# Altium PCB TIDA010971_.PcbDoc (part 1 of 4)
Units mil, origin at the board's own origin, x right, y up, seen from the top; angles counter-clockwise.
Board outline 4500 x 6000 mil, 2 copper layers (F.CU, B.CU), stack 60.617 mil thick; 280 components, 124 nets, 681 pads, 871 vias.
Unrouted connection lines stored in the file: 1.
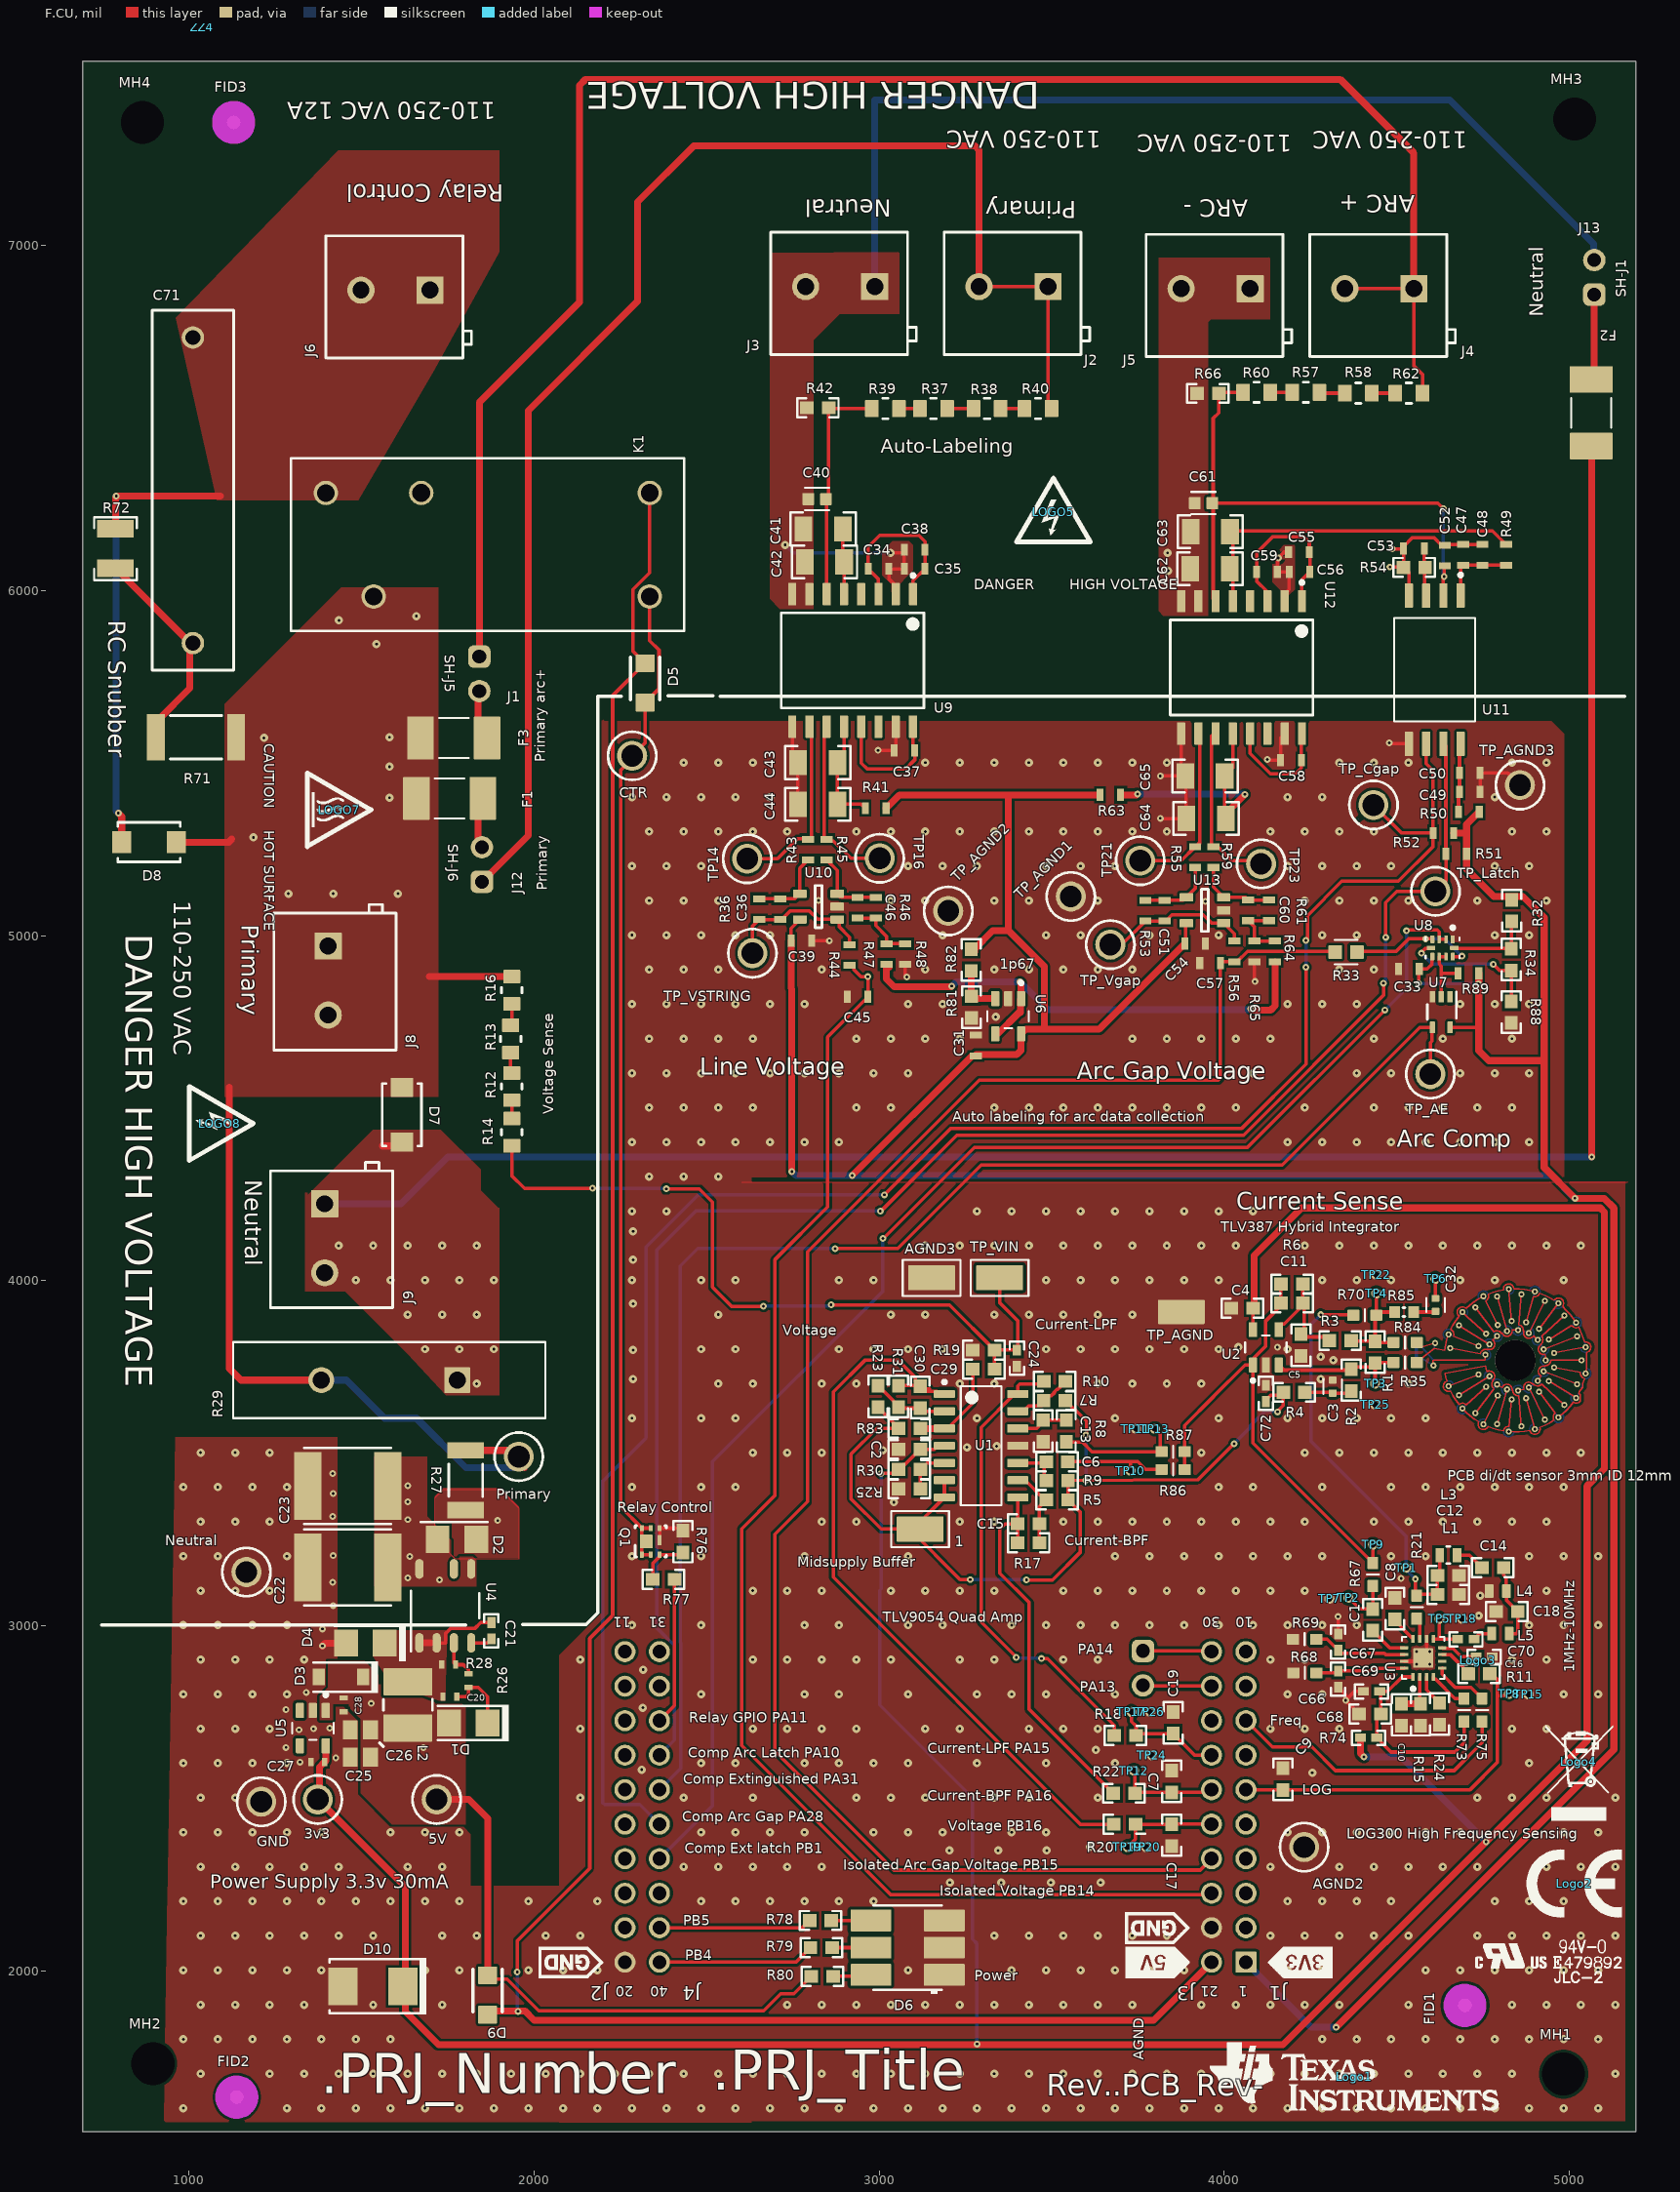
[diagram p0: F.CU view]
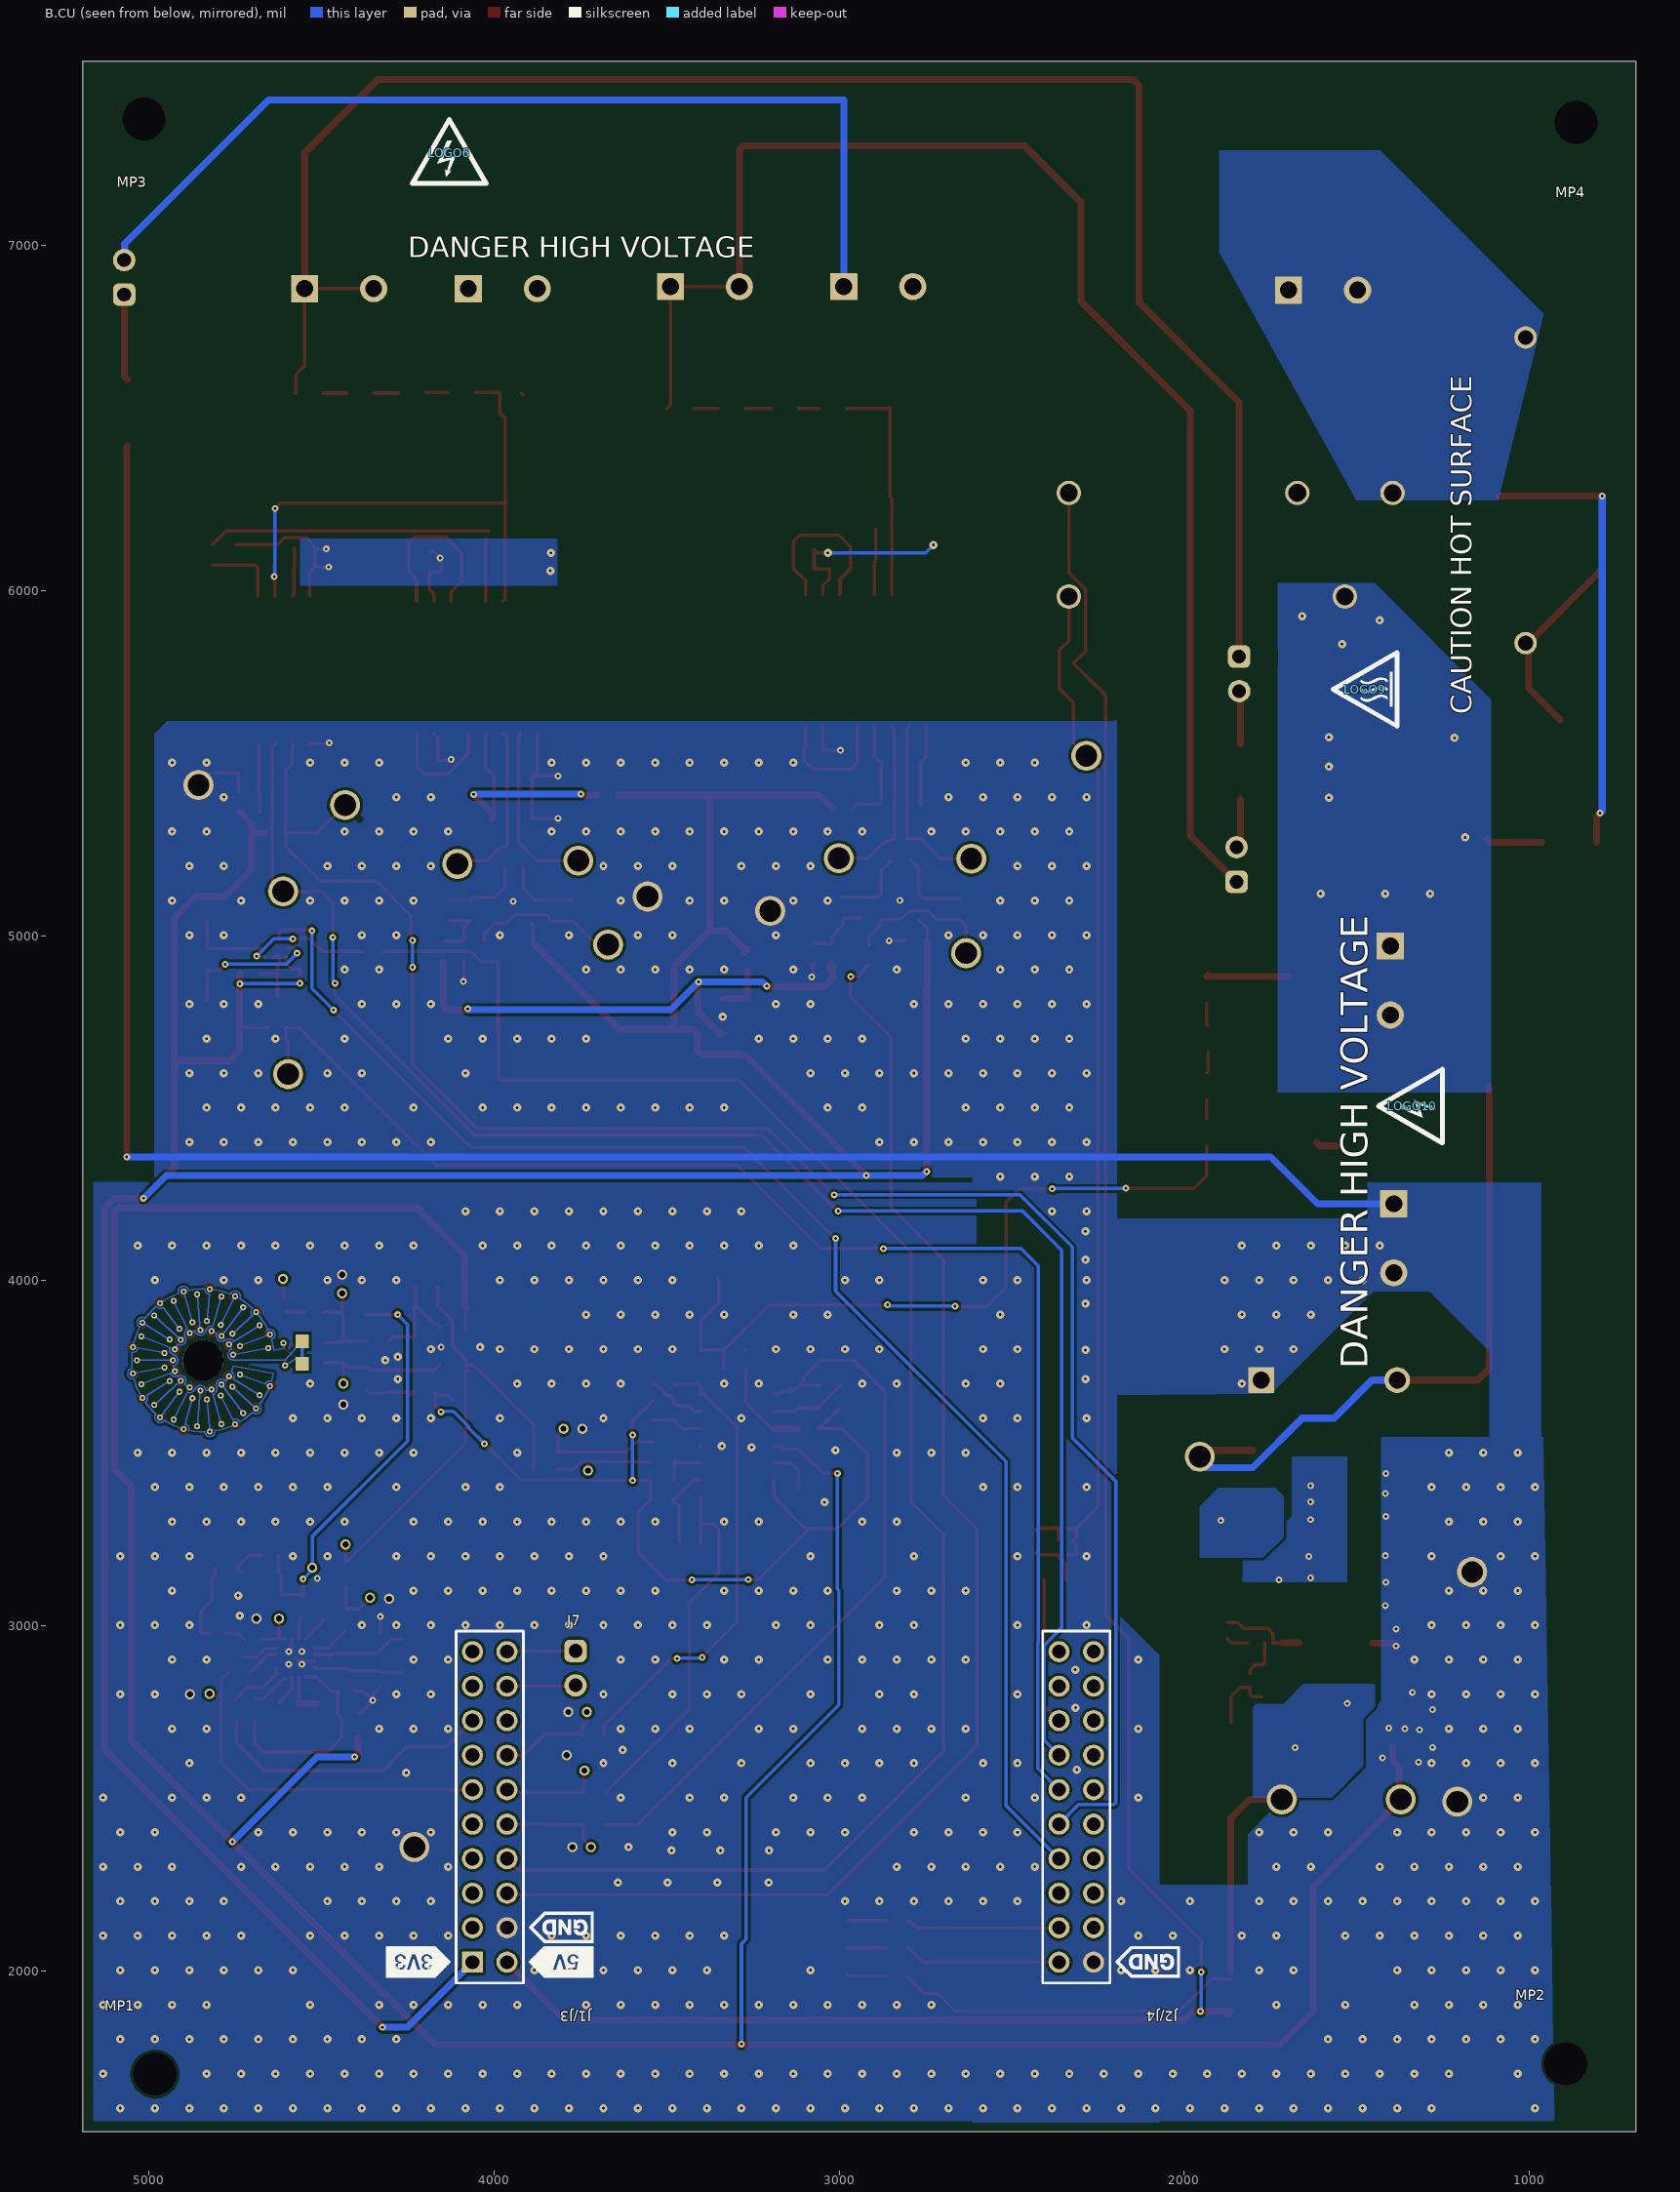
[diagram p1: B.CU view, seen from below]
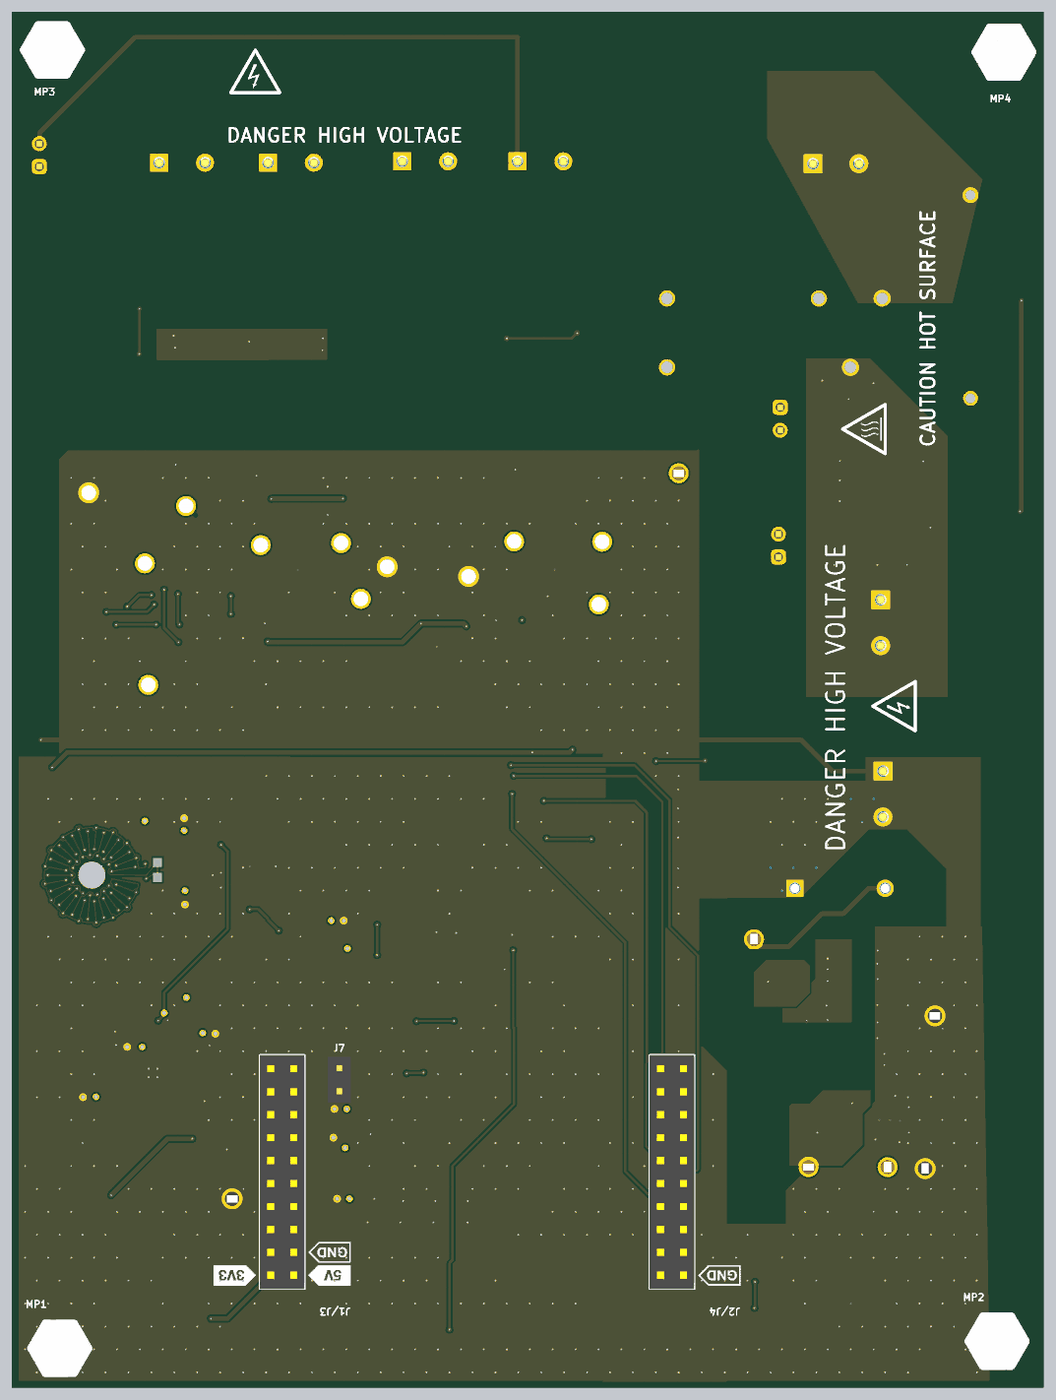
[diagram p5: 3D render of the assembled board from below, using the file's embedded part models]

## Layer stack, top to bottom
Top Solder: solder mask 0.4, Solder Resist, Dk 3.5
F.CU: signal copper 0.7087
Dielectric1: core 59.2, FR-4 High Tg, Dk 4.8
B.CU: signal copper 0.7087
Bottom Solder: solder mask 0.4, Solder Resist, Dk 3.5

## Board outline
692,1534 5192,1534 5192,7534 692,7534

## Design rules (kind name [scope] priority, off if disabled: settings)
AcuteAngle [All] p1: minimum=4.50000000000000E+0001 checktracksonly=FALSE
AssemblyTestPointUsage [All] p1: valid=2
BoardOutlineClearance BoardOutlineClearance_MountingHoles [OnCopper and InComponentClass('Mounting Holes')] p1: gap=39.37 ignorepadtopadclearanceinfootprint=FALSE
BoardOutlineClearance BoardOutlineClearance_Poly [OnCopper and IsPoly] p2: gap=25 ignorepadtopadclearanceinfootprint=FALSE
BoardOutlineClearance [OnCopper and Not InComponentClass('Logo') and not InComponentClass('FiducialMark') and not InRegion(1000,500,4000,800) and not InPoly] p3: gap=40 ignorepadtopadclearanceinfootprint=FALSE
Clearance Clearance_1 [InNetClass('low voltage') And OnMid vs InNetClass('high voltage') And OnMid] p1: gap=80 ignorepadtopadclearanceinfootprint=FALSE
Clearance Clearance_2 [InNetClass('low voltage') And (ExistsOnLayer('F.CU') Or ExistsOnLayer('B.CU')) vs InNetClass('high voltage') And (ExistsOnLayer('F.CU') Or ExistsOnLayer('B.CU'))] p2: gap=80 ignorepadtopadclearanceinfootprint=FALSE
Clearance Clearance_3 [InNetClass('low voltage') vs InNetClass('high voltage')] p3: gap=10 ignorepadtopadclearanceinfootprint=FALSE except(0: Arc-Hole Track-Hole SMDPad-Hole THPad-Hole Via-Hole Fill-Hole Poly-Hole Region-Hole Text-Hole)
Clearance Clearance_4 [OnMid vs OnMid] p4: gap=7.87 ignorepadtopadclearanceinfootprint=FALSE
Clearance Clearance_5 [(ExistsOnLayer('F.CU') Or ExistsOnLayer('B.CU')) vs (ExistsOnLayer('F.CU') Or ExistsOnLayer('B.CU'))] p5: gap=7.87 ignorepadtopadclearanceinfootprint=FALSE
Clearance [All] p6: gap=10 ignorepadtopadclearanceinfootprint=FALSE except(0: Arc-Hole Track-Hole SMDPad-Hole THPad-Hole Via-Hole Fill-Hole Poly-Hole Region-Hole Text-Hole)
ComponentClearance ComponentClearance_MountingHoles_FiducialMarks [InComponentClass('Mounting Holes') vs InComponentClass('FiducialMark')] p1: gap=50 collisioncheckmode=3 verticalgap=10 showdistances=FALSE
ComponentClearance ComponentClearance_Shunt [InComponentClass('Header') vs InComponentClass('Shunt')] p2: gap=0 collisioncheckmode=3 verticalgap=0 showdistances=FALSE
ComponentClearance ComponentClearance_Logo [InComponentClass('Logo')] p3: gap=30 collisioncheckmode=3 verticalgap=10 showdistances=FALSE
ComponentClearance ComponentClearance_ScrewToNut [(HasFootprint('NY PMS 440 0025 PH')) vs (HasFootprint('Keystone_1902C'))] p4: gap=5 collisioncheckmode=3 verticalgap=10 showdistances=FALSE
ComponentClearance ComponentClearance_MountingHoles [InComponentClass('Mounting Holes')] p5: gap=100 collisioncheckmode=3 verticalgap=100000 showdistances=FALSE
ComponentClearance ComponentClearance_SmallPassives [HasFootprint('0201*') or HasFootprint('0402*') or HasFootprint('0508') or HasFootprint('0603*') or HasFootprint('0612') or HasFootprint('0805*') or HasFootprint('0815*') or HasFootprint('0830*') or HasFootprint('1206*') or HasFootprint('1210*') or HasFootprint('1808*') or HasFootprint('1812*') or HasFootprint('1825*') or HasFootprint('2010*') or HasFootprint('2220*') or HasFootprint('2225*') or HasFootprint('2512*') or HasFootprint('2728*') or HasFootprint('3518*') vs HasFootprint('0201*') or HasFootprint('0402*') or HasFootprint('0508') or HasFootprint('0603*') or HasFootprint('0612') or HasFootprint('0805*') or HasFootprint('0815*') or HasFootprint('0830*') or HasFootprint('1206*') or HasFootprint('1210*') or HasFootprint('1808*') or HasFootprint('1812*') or HasFootprint('1825*') or HasFootprint('2010*') or HasFootprint('2220*') or HasFootprint('2225*') or HasFootprint('2512*') or HasFootprint('2728*') or HasFootprint('3518*')] p6: gap=14.96 collisioncheckmode=3 verticalgap=10 showdistances=FALSE
ComponentClearance ComponentClearance_THtoSMT [IsThruComponent vs IsSMTComponent] p7: gap=30 collisioncheckmode=3 verticalgap=30 showdistances=FALSE
ComponentClearance ComponentClearance_THtoTH [IsThruComponent vs IsThruComponent] p8: gap=20 collisioncheckmode=3 verticalgap=30 showdistances=FALSE
ComponentClearance [All] p9: gap=20 collisioncheckmode=3 verticalgap=10 showdistances=FALSE
FabricationTestPointUsage TestPointUsage [All] p1: valid=2 allowmultiple=FALSE
FabricationTestpoint Testpoint [All] p1: side=3 testpointundercomponent=TRUE minsize=40 maxsize=100 preferedsize=60 minholesize=0 maxholesize=40 preferedholesize=32 testpointgrid=1 allowsidetop=TRUE allowsidebottom=TRUE usegrid=TRUE gridtolerance=0.01
FanoutControl Fanout_LCC [IsLCC] p1: bgadir=Out bgaviamode=Centered fanoutstyle=Auto fanoutdirection=Alternating viagrid=1 // Fanout_LCC (Default Rule)
FanoutControl Fanout_BGA [IsBGA] p2: bgadir=Out bgaviamode=Centered fanoutstyle=Auto fanoutdirection=Alternating viagrid=1 // Fanout_BGA (Default Rule)
FanoutControl Fanout_Default [All] p4: bgadir=Out bgaviamode=Centered fanoutstyle=Auto fanoutdirection=Alternating viagrid=1 // Fanout_Default (Default Rule)
FanoutControl Fanout_Small [(CompPinCount < 5)] p5: bgadir=Out bgaviamode=Centered fanoutstyle=Auto fanoutdirection=OutThenIn viagrid=1 // Fanout_Small (Default Rule)
HoleSize [All] p1: absolutevalues=TRUE maxlimit=251 minlimit=7.87 maxpercent=80.000 minpercent=20.000
MinimumAnnularRing MinimumAnnularRing_ThermalPadVias [IsVia and InAnyComponent] p1: minimumring=5.91
MinimumAnnularRing [All] p2: minimumring=4.92
MinimumSolderMaskSliver MinimumSolderMaskSliver_Logo [InComponentClass('Logo') vs InComponentClass('Logo')] p1: minsoldermaskwidth=0.7
MinimumSolderMaskSliver [All] p2: minsoldermaskwidth=3.94
PlaneConnect [All] p1: planeconnectstyle=Direct reliefexpansion=10 reliefentries=4 reliefconductorwidth=10 reliefairgap=10
PolygonConnect PolygonConnect_1 [All vs IsNamedPolygon('F.CU_GND_ISO_AMC23C12_P064')] p1: thpad.connectstyle=Direct thpad.reliefconductorwidth=10 thpad.reliefentries=4 thpad.polygonreliefangle="90 Angle" thpad.airgapwidth=5 smdpad.connectstyle=Direct smdpad.reliefconductorwidth=10 smdpad.reliefentries=4 smdpad.polygonreliefangle="90 Angle" smdpad.airgapwidth=10 via.connectstyle=Relief via.reliefconductorwidth=10 via.reliefentries=4 via.polygonreliefangle="90 Angle" via.airgapwidth=10
PolygonConnect [All] p2: connectstyle=Direct reliefconductorwidth=10 reliefentries=4 polygonreliefangle="90 Angle" airgapwidth=10
RoutingVias [All] p1: holewidth=28 width=50 viastyle="Through Hole" minholewidth=28 minwidth=50 maxholewidth=28 maxwidth=50 useviatemplates=TRUE viatemplateguid#1={BF80594A-C1D7-457B-8FD0-876E30155DD2} viatemplatename#1=v50h20
SilkToBoardRegionClearance [Not ((IsComment or IsDesignator) And (Hide <> 'False')) and not InRegion(1000,500,4000,800)] p1:
SilkToSilkClearance SilkToSilkClearance_Pb-FreeLogo [(HasFootprint('Pb-Free_Overlay_Medium') OR HasFootprint('Pb-Free_Overlay_Small')) vs (HasFootprint('Pb-Free_Overlay_Medium') OR HasFootprint('Pb-Free_Overlay_Small'))] p1: silktosilkclearance=0
SilkToSilkClearance [All] p2: silktosilkclearance=3.94
SilkToSolderMaskClearance SilkToComponentPadClearance [(IsPad or IsFill or IsRegion) and InAnycomponent] p1: minsilkscreentomaskgap=5 clearancetoexposedcopper=TRUE
SilkToSolderMaskClearance "Silk to Solder Mask Opening" [All] p2: minsilkscreentomaskgap=3.94 clearancetoexposedcopper=FALSE
SolderMaskExpansion SolderMask_tentVias [IsVia] p1: expansion=4 istentingtop=TRUE
SolderMaskExpansion [All] p2: expansion=1.97 istentingtop=FALSE
UnRoutedNet [All] p1: checkbadconnections=TRUE
Width MaxMinWidth_1 [All] p1: maxlimit=20 minlimit=3.94 preferedwidth=10 minimp=50.000000 maximp=50.000000 favimp=50.000000
Width [All] p2: maxlimit=20 minlimit=5 preferedwidth=10 minimp=50.000000 maximp=50.000000 favimp=50.000000
15 further rules are at their usual default settings.

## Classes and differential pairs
net class "low voltage": 3v3 3v3USB 5v_led 5vUSB ADC_Log "ADC_Voltage sense" AFEen BP_in COMP_VGap COMP_VGap_LATCH COMP_VGap_VString Current_BP Current_LP FreqDetect GND_iso_AMC23C12 LNA_en LNA_O Log+ Log- midSupply NetC1_1 NetC1_2 NetC3_2 NetC5_2 NetC6_1 NetC8_2 NetC10_2 NetC13_2 NetC14_1 NetC14_2 NetC15_1 NetC15_2 NetC20_1 NetC20_2 NetC21_1 NetC24_1 NetC29_1 NetC30_1 NetC30_2 NetC34_1 NetC34_2 NetC36_1 NetC36_2 NetC37_1 NetC40_2 NetC41_1 NetC43_1 NetC46_1 NetC46_2 NetC47_1 NetC49_1 NetC51_1 NetC51_2 NetC52_1 NetC53_1 NetC55_1 NetC58_1 NetC60_1 NetC60_2 NetC64_1 NetC68_2 NetC70_2 NetC71_1 NetCTR_1 NetD6_4 NetD6_5 NetD6_6 NetF1_1 NetF2_1 NetF3_1 NetJ1_1 NetJ2_1 NetQ1_3 NetR7_2 NetR10_2 NetR11_1 NetR12_1 NetR12_2 NetR13_1 NetR24_1 NetR25_2 NetR26_1 NetR32_1 NetR33_1 NetR37_1 NetR37_2 NetR38_1 NetR57_1 NetR57_2 NetR58_1 NetR73_1 NetR75_2 PA13_UART0-TX_XDS PA14_UART0-RX_XDS relayGPIO Rogo+ Rogo- V_Gap V_String VCC_iso_AMC23C12 VGap_Diff_N VGap_Diff_P VString_Diff_N VString_Diff_P
net class "high voltage": hv2 HVIN NetD2_2 Primary RelayControl
component class Shunt: SH-J1 SH-J5 SH-J6
component class Header: J1 J7 J12 J13
component class FiducialMark: FID1 FID2 FID3
polygon class HighVoltage: F.CU_5V_P059
component class TIDA010971_Power: 3v3 5V C20 C21 C22 C23 C25 C26 C27 C28 D1 D2 D3 D4 D7 D10 GND J8 J9 L2 Neutral Primary R26 R27 R28 R29 U4 U5
component class TIDA010971_Connectors_MCU_Labeling: C71 CTR D5 D6 D8 D9 J1/J3 J2/J4 J6 J7 K1 Q1 R71 R72 R76 R77 R78 R79 R80
component class TIDA010971_AutoLabeling: C31 C33 C34 C35 C36 C37 C38 C39 C40 C41 C42 C43 C44 C45 C46 C47 C48 C49 C50 C51 C52 C53 C54 C55 C56 C57 C58 C59 C60 C61 C62 C63 C64 C65 F1 F2 F3 J1 J2 J3 J4 J5 J12 J13 R32 R33 R34 R36 R37 R38 R39 R40 R41 R42 R43 R44 R45 R46 R47 R48 R49 R50 R51 R52 R53 R54 R55 R56 R57 R58 R59 R60 R61 R62 R63 R64 R65 R66 R81 R82 R88 R89 SH-J1 SH-J5 SH-J6 TP14 TP16 TP21 TP23 TP_AE TP_AGND1 TP_AGND2 TP_AGND3 TP_Cgap TP_Latch TP_Vgap TP_VSTRING U6 U7 U8 U9 U10 U11 U12 U13
component class TIDA010971_AFE: 1 AGND2 AGND3 C1 C2 C3 C4 C5 C6 C7 C8 C9 C10 C11 C12 C13 C14 C15 C16 C17 C18 C19 C24 C29 C30 C32 C66 C67 C68 C69 C70 C72 L1 L3 L4 L5 R1 R2 R3 R4 R5 R6 R7 R8 R9 R10 R11 R12 R13 R14 R15 R16 R17 R18 R19 R20 R21 R22 R23 R24 R25 R30 R31 R35 R67 R68 R69 R70 R73 R74 R75 R83 R84 R85 R86 R87 TP1 TP2 TP3 TP4 TP5 TP6 TP7 TP8 TP9 TP10 TP11 TP12 TP13 TP15 TP17 TP18 TP19 TP20 TP22 TP24 TP25 TP26 TP_AGND TP_VIN U1 U2 U3
component class Logo: Logo1
component class TIDA010971_Hardware: FID1 FID2 FID3 Logo1 Logo2 Logo3 Logo4 LOGO5 LOGO6 LOGO7 LOGO8 LOGO9 LOGO10 MH1 MH2 MH3 MH4 MP1 MP2 MP3 MP4 ZZ1 ZZ2 ZZ3 ZZ4
component class AssemblyNote: ZZ1 ZZ2 ZZ3 ZZ4

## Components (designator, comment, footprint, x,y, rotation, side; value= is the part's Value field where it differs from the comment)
1 "S1751-46R" FP-S1751-46R_SMT_TEST_POINT_3MM25_1MM65-MFG 3118.56,3279.95 r180 top
3v3 "5010" Keystone5010 1372.77,2496.66 r180 top
5V "5010" Keystone5010 1717.36,2496.66 r90 top
AGND2 "HS1_GND" Keystone5006 4231.31,2358.55 r0 top
AGND3 "S1751-46R" FP-S1751-46R_SMT_TEST_POINT_3MM25_1MM65-MFG 3151.52,4008.52 r180 top
C1 "GRM1885C1E102JA01D" 0603 4430.17,3017.24 r90 top value=1000pF
C2 "0603ZC104KAT2A" 0603 3087.47,3511.35 r0 top value=0.1uF
C3 "GMC04X7R105K10NT" FP-GMC04X7R105K10NT_0402-MFG 4314,3693 r270 top value=1µF
C4 "0603ZC104KAT2A" 0603 4052,3920.28 r0 top value=0.1uF
C5 "C0603C271J5GACTU" 0603 4222,3813.5 r90 top value=270pF
C6 "06035A101JAT2A" 0603 3515.33,3475.54 r0 top value=100pF
C7 "06035A101JAT2A" 0603 3847.78,2548.81 r90 top value=100pF
C8 "06035C104JAT2A" 0603 4493.95,3049.8 r270 top value=0.1uF
C9 "GRM1885C1H470JA01D" 0603 4169.78,2555.46 r90 top value=47pF
C10 "GRM1885C1E102JA01D" 0603 4513.58,2742.1 r90 top value=1000pF
C11 "C0603C271J5GACTU" 0603 4196.22,3935.08 r0 top value=270pF
C12 "GRM1885C1H131JA01D" 0603 4649.04,3145.8 r0 top value=130pF
C13 "0603ZC104KAT2A" 0603 3475.33,3564.54 r90 top value=0.1uF
C14 "GRM1885C1H152JA01D" 0603 4778,3168.28 r180 top value=1500pF
C15 "06035A470JAT2A" 0603 3432.7,3295.43 r0 top value=47pF
C16 "CL05B392KB5NNNC" 0402 4753,2910 r0 top value=3900pF
C17 "GRM1885C1H470JA01D" 0603 3847.28,2393 r270 top value=47pF
C18 "GRM1885C1H331JA01D" 0603 4818.95,3041 r180 top value=330pF
C19 "06035A101JAT2A" 0603 3851.56,2718.73 r90 top value=100pF
C20 "GRM155R71H153KA12D" 0402S 1755.43,2795.15 r180 top value=0.015uF
C21 "GRM155R61C105MA12D" 0402 1875.74,2985.95 r90 top value=1uF
C22 "CKG57NX7T2W225M500JH" CKG57N 1459.61,3168.87 r180 top value=2.2uF
C23 "CKG57NX7T2W225M500JH" CKG57N 1459.61,3405.37 r180 top value=2.2uF
C24 "GRM1555C1H2R4CA01D" 0402 3398.7,3775.36 r270 top value=2.4pF
C25 "GRM21BR61A476ME15L" 0805L 1496.3,2618.71 r180 top value=47uF
C26 "GRM21BR61A476ME15L" 0805L 1496.3,2698.37 r180 top value=47uF
C27 "GRM155R61A105ME15D" 0402S 1372.77,2604.93 r180 top value=1uF
C28 "GRM155R61A104KA01D" 0402S 1447.99,2771.12 r270 top value=0.1uF
C29 "CL10B103KB8NCNC" 0603 3302.8,3743.93 r0 top value=0.01uF
C30 "GRM1885C1H470JA01D" 0603 3118.56,3662.23 r270 top value=47pF
C31 "C0603C104K5RACAUTO" 0603S 3280.22,4681.56 r90 top value=0.1uF
C32 "GMC04X7R105K10NT" FP-GMC04X7R105K10NT_0402-MFG 4612,3929.81 r270 top value=1µF
C33 "C0603C104J3RACTU" 0603S 4534.82,4903.23 r0 top value=0.1uF
C34 "06033C105KAT2A" 0603S 2997.75,6063.43 r0 top value=1uF
C35 "C0603C102K5RACTU" 0603S 3102.67,6063.43 r180 top value=1000pF
C36 "CL10C102JB8NNNC" 0603S 2713.1,5077.03 r90 top value=1000pF
C37 "C0603C104K5RACAUTO" 0603S 3072.67,5537.12 r180 top value=0.1uF
C38 "C0603C104K5RACAUTO" 0603S 3102.67,6118.55 r0 top value=0.1uF
C39 "C0603C104J3RAC" 0603S 2774.43,4985.88 r0 top value=0.1uF
C40 "C0603X102K5RAC7867" FP-C0603X102K5RAC7867_0603-MFG 2820.05,6265.44 r0 top value=1nF
C41 "12065C102KAT2A" 1206 2837.3,6178.78 r180 top value=1000pF
C42 "C1206C104K5RACTU" 1206 2841.24,6083.12 r180 top value=0.1uF
C43 "12065C102KAT2A" 1206 2821.56,5501.68 r180 top value=1000pF
C44 "12063C105KAT2A" 1206 2821.56,5380.95 r180 top value=1uF
C45 "CL10C102JB8NNNC" 0603S 2937.27,4823.04 r180 top value=1000pF
C46 "CL10C102JB8NNNC" 0603S 2937.27,5080.85 r270 top value=1000pF
C47 "06033C105KAT2A" 0603S 4691.81,6103.66 r90 top value=1uF
C48 "06033C104KAT2A" 0603S 4748.16,6103.66 r90 top value=0.1uF
C49 "06033C104KAT2A" 0603S 4711.5,5416.66 r0 top value=0.1uF
C50 "06033C105KAT2A" 0603S 4711.5,5471.77 r0 top value=1uF
C51 "CL10C102JB8NNNC" 0603S 3826.89,5072.59 r90 top value=1000pF
C52 "C0603C100J5GACTU" 0603S 4639,6102 r90 top value=10pF
C53 "06033C104KAT2A" 0603S 4549.23,6122.3 r180 top value=0.1uF
C54 "C0603C104J3RAC" 0603S 3915.44,4977.14 r0 top value=0.1uF
C55 "06033C105KAT2A" 0603S 4216.14,6111.68 r180 top value=1uF
C56 "C0603C102K5RACTU" 0603S 4217.73,6054.71 r180 top value=1000pF
C57 "CL10C102JB8NNNC" 0603S 3958.75,4920.57 r180 top value=1000pF
C58 "C0603C104K5RACAUTO" 0603S 4193.28,5509.18 r180 top value=0.1uF
C59 "C0603C104K5RACAUTO" 0603S 4123.62,6054.71 r180 top value=0.1uF
C60 "CL10C102JB8NNNC" 0603S 4069.03,5073.62 r270 top value=1000pF
C61 "C0603X102K5RAC7867" FP-C0603X102K5RAC7867_0603-MFG 3939.64,6253.81 r0 top value=1nF
C62 "12065C102KAT2A" 1206 3958.87,6063.39 r180 top value=1000pF
C63 "C1206C104K5RACTU" 1206 3959.33,6171.36 r180 top value=0.1uF
C64 "12065C102KAT2A" 1206 3946.84,5339.5 r180 top value=1000pF
C65 "12063C105KAT2A" 1206 3943.91,5462.92 r180 top value=1uF
C66 "0402B103K6R3CT" 0402 4329.9,2845.35 r90 top value=0.01uF
C67 "0402B103K6R3CT" 0402 4329.9,2952.39 r90 top value=0.01uF
C68 "GRM188Z71A106MA73D" 0603 4422.3,2744.58 r0 top value=10uF
C69 "GRM155R70J103KA01D" 0402 4426.99,2809.92 r0 top value=0.01uF
C70 "CL05B392KB5NNNC" 0402 4700,2961 r0 top value=3900pF
C71 "B32933A3104K000" B32933_600x1500x2650 1011,6290.91 r90 top value=0.1uF
C72 "C0402C102J3GACTU" 0402 4120.26,3673.35 r90 top value=1000pF
CTR "" Keystone5005 2283.9,5521.33 r0 top
D1 "CD1408-FU1600" Diode_1408 1809,2718.12 r180 top value=600V
D2 "CD1408-FU1600" Diode_1408 1776.11,3250.62 r0 top value=600V
D3 "DDZ8V2C-7" SOD-123 1440.2,2851.27 r180 top value=8.2V
D4 "CD1408-FU1600" Diode_1408 1510.61,2949.87 r180 top value=600V
D5 "" DO-219AB 2321.3,5732.54 r270 top value=20V
D6 "AAAF5060QBFSURZGS" AAAF5060QBFSURZGS 3082.1,2067.22 r180 top value=Rgb
D7 "SMAJ400CA" SMA_Bi 1616.53,4481 r90 top value=400V
D8 "SMAJ400CA" SMA_Bi 884,5271 r180 top value=400V
D9 "" DO-219AB 1865.11,1929.99 r270 top value=20V
D10 "SMBJ3V3-E3/52" SMB 1532.49,1955 r180 top value=3.3V
F1 "0476005.MR" FP-0476005.MR_SMT_FUSE_6MM1_2MM69-MFG 1755,5398 r180 top
F2 "0476005.MR" FP-0476005.MR_SMT_FUSE_6MM1_2MM69-MFG 5063.13,6515.67 r270 top
F3 "0476005.MR" FP-0476005.MR_SMT_FUSE_6MM1_2MM69-MFG 1767,5573 r180 top
FID1 "Fiducial" Fiducial10-30 4697.41,1899.72 r90 top
FID2 "Fiducial" Fiducial10-30 1138,1634 r0 top
FID3 "Fiducial" Fiducial10-30 1129.11,7357 r0 top
GND "5011" Keystone5011 1209,2490 r180 top
J1 "TSW-102-07-G-S" TSW-102-07-G-S 1841,5759 r270 top
J1/J3 "SSQ-110-03-T-D" BoosterPack_40pin_J1J3 4012.78,2475 r0 bottom
J2 "ED120/2DS" On-Shore_ED120_2DS 3389.21,6881.14 r180 top
J2/J4 "SSQ-110-03-T-D" BoosterPack_40pin_J2J4 2313,2475 r0 bottom
J3 "ED120/2DS" On-Shore_ED120_2DS 2886.74,6881.14 r180 top
J4 "ED120/2DS" On-Shore_ED120_2DS 4449.23,6875.29 r180 top
J5 "ED120/2DS" On-Shore_ED120_2DS 3974.85,6875.29 r180 top
J6 "ED120/2DS" On-Shore_ED120_2DS 1598,6871 r180 top
J7 "TSW-102-07-G-S" TSW-102-07-G-S 3764.28,2877.3 r270 bottom
J8 "ED120/2DS" On-Shore_ED120_2DS 1403,4870 r270 top
J9 "ED120/2DS" On-Shore_ED120_2DS 1393,4123 r270 top
J12 "TSW-102-07-G-S" TSW-102-07-G-S 1848.54,5206.17 r90 top
J13 "TSW-102-07-G-S" TSW-102-07-G-S 5072.14,6908.04 r90 top
K1 "RTB14005F" RELAY_RTB14 1864.56,6133.28 r180 top
L1 "LQM18FN100M00D" 0603 4649.04,3090.8 r180 top value=10uH
L2 "744045681" WE-LQ_1812 1634.09,2770.72 r270 top value=680uH
L3 "0603AF-821KRB" 0603AF 4649.45,3204.65 r180 top value=820nH
L4 "0603LS-392XJLB" 0603LS_B2 4792.62,3100.49 r0 top value=3.9uH
L5 "0603LS-331XJLB" 0603LS_B1 4800.1,2977.39 r180 top value=330nH
Logo1 "Texas Instruments" TI_Stacked_Overlay_Small 4376.52,1693.74 r0 top
Logo2 "CE Mark" CE_Mark_5mm 5014,2253 r0 top
Logo3 "FCC disclaimer" FCC_disclaimer 4734,2900.83 r0 top
Logo4 "WEEE logo" WEEE_Minimum 5027,2607 r0 top
LOGO5 "DANGER HIGH VOLTAGE" IEC_HighVoltage_Small 3504.66,6228.79 r0 top
LOGO6 "DANGER HIGH VOLTAGE" IEC_HighVoltage_Small 4130.03,7268.5 r180 bottom
LOGO7 "CAUTION HOT SURFACE" IEC_HotSurface_Small 1435,5365 r270 top
LOGO8 "DANGER HIGH VOLTAGE" IEC_HighVoltage_Small 1089,4456 r270 top
LOGO9 "CAUTION HOT SURFACE" IEC_HotSurface_Small 1476,5714 r90 bottom
LOGO10 "DANGER HIGH VOLTAGE" IEC_HighVoltage_Small 1339.74,4505.99 r90 bottom
MH1 "MTG_NoPads" NPTH125mil 4983,1700.67 r0 top
MH2 "MTG_NoPads" NPTH125mil 895.09,1730.94 r0 top
MH3 "MTG_NoPads" NPTH125mil 5015,7367 r0 top
MH4 "MTG_NoPads" NPTH125mil 865,7357 r0 top
MP1 "4806" FP-4806_HEX_STNDFF_4-40-MFG 4983,1707.23 r180 bottom
MP2 "4806" FP-4806_HEX_STNDFF_4-40-MFG 895.09,1737.5 r180 bottom
MP3 "4806" FP-4806_HEX_STNDFF_4-40-MFG 5015,7367 r180 bottom
MP4 "4806" FP-4806_HEX_STNDFF_4-40-MFG 865,7357 r180 bottom
Neutral "5011" Keystone5011 1166,3155.72 r90 top
Primary "5010" Keystone5010 1955.22,3490.16 r180 top
Q1 "CSD13202Q2" DQK0006C 2337.74,3244.5 r90 top value=12V
R1 "RT0603BRD07221RL" 0603 4437,3793 r270 top value=221
R2 "CRCW060310R0FKEAHP" 0603 4368,3712 r270 top value=10.0
R3 "RG1608P-2210-B-T5" 0603 4335.81,3826.3 r180 top value=221
R4 "CRCW060310R0FKEAHP" 0603 4202.49,3676.72 r180 top value=10.0
R5 "RT0603DRE074K02L" 0603 3515.5,3364.93 r180 top value=4.02k
R6 "RT0603BRD07562KL" 0603 4196.22,3990.46 r180 top value=562k
R7 "RT0603BRD0710K1L" 0603 3507.83,3652.54 r180 top value=10.1k
R8 "ERJ-3EKF2702V" 0603 3541.83,3564.54 r90 top value=27.0k
R9 "RC0603FR-07270KL" 0603 3515.5,3420.93 r0 top value=270k
R10 "CRCW0603100KJNEAC" 0603 3508.33,3708.54 r180 top value=100k
R11 "RG1608P-511-B-T5" 0603 4738,2861 r0 top value=510
R12 "CRCW0805316KFKEA" 0805_HV1 1935.04,4562.76 r270 top value=316k
R13 "CRCW0805316KFKEA" 0805_HV1 1931.83,4700.8 r270 top value=316k
R14 "CRCW0805316KFKEA" 0805_HV1 1935.04,4430.5 r270 top value=316k
R15 "RC0603FR-0730KL" 0603 4568.58,2742.1 r90 top value=30.0k
R16 "CRCW0805316KFKEA" 0805_HV1 1935.04,4841.98 r90 top value=316k
R17 "RT0603DRE0764K9L" 0603 3432.7,3240.76 r180 top value=64.9k
R18 "CRCW06031K10JNEA" 0603 3712.78,2682.12 r0 top value=1.1k
R19 "RC0603FR-07619RL" 0603 3302.8,3798.98 r0 top value=619
R20 "RG1608P-511-B-T5" 0603 3710.86,2424.5 r0 top value=510
R21 "RC0603FR-100RL" FP-RC0603FR-100RL_0603-MFG 4557.53,3054.01 r90 top value=0
R22 "CRCW06031K10JNEA" 0603 3709.5,2514.36 r0 top value=1.1k
R23 "RC0603FR-076K8L" 0603 2996.31,3664.63 r90 top value=6.80k
R24 "RG1608P-563-B-T5" 0603 4623.42,2744.58 r270 top value=56.0k
R25 "CRCW0603100KJNEAC" 0603 3087.5,3396.93 r0 top value=100k
R26 "CRCW040238K3FKED" 0402S 1809.29,2841.15 r270 top value=38.3k
R27 "CRCW2010470RFKEF" 2010L 1801.42,3421.86 r270 top value=470
R28 "ERJ-2RKF1002X" 0402S 1752.2,2887.15 r0 top value=10.0k
R29 "MOV-20D431K" FP-MOV-20D431K_RADIAL-MFG 1580,3712 r180 top
R30 "CRCW0603100KJNEAC" 0603 3087.47,3452.98 r180 top value=100k
R31 "RC0603FR-0768K1L" 0603 3055.84,3664.63 r90 top value=68.1k
R32 "M55342K12B10E0T" 0603 4833.07,5072.59 r90 top value=10.0k
R33 "CR0603-10W-000T" FP-CR0603-10W-000T_0603-MFG 4353.02,4952.34 r180 top value=0uΩ
R34 "RC0603FR-0791KL" 0603 4831.73,4930.69 r90 top value=91.0k
R35 "RC0603FR-100RL" FP-RC0603FR-100RL_0603-MFG 4524,3763 r180 top value=0
R36 "RT0603BRD0716K5L" 0603S 2652.09,5077.03 r270 top value=16.5k
R37 "CRCW0805316KFKEA" 0805_HV1 3157.37,6527.87 r180 top value=316k
R38 "CRCW0805316KFKEA" 0805_HV1 3312.34,6527.87 r180 top value=316k
R39 "CRCW0805316KFKEA" 0805_HV1 3017.84,6527.87 r180 top value=316k
R40 "CRCW0805316KFKEA" 0805_HV1 3459.98,6527.87 r0 top value=316k
R41 "RC0603JR-070RL" 0603S 2989.75,5369.41 r0 top value=0
R42 "RC0603FR-073K24L" 0603 2822.01,6530.2 r0 top value=3.24k
R43 "RT0603BRD0710KL" 0603S 2794,5249.52 r270 top value=10.0k
R44 "CRCW060310R0JNEA" 0603S 2914.22,4944.06 r270 top value=10
R45 "RT0603BRD0710KL" 0603S 2847.75,5249.52 r270 top value=10.0k
R46 "RT0603BRD0716K5L" 0603S 2989.78,5080.85 r90 top value=16.5k
R47 "RMCF0603ZT0R00" 0603S 3020.97,4946.54 r90 top value=0
R48 "RMCF0603ZT0R00" 0603S 3075.48,4946.54 r270 top value=0
R49 "RC0603JR-070RL" 0603S 4816.53,6103.66 r270 top value=0
R50 "RC0603JR-070RL" 0603S 4708.69,5359.18 r0 top value=0
R51 "RC0603JR-074K7L" 0603S 4672.13,5237.48 r0 top value=4.7k
R52 "RC0603JR-074K7L" 0603S 4634.82,5297.51 r0 top value=4.7k
R53 "RT0603BRD0716K5L" 0603S 3771.18,5072.59 r270 top value=16.5k
R54 "RC0603JR-072KL" 0603 4550.38,6067.38 r0 top value=2.0k
R55 "RT0603BRD0710KL" 0603S 3915.44,5227.62 r270 top value=10.0k
R56 "CRCW060310R0JNEA" 0603S 4029.19,4954.66 r270 top value=10
R57 "CRCW0805316KFKEA" 0805_HV1 4236.2,6574.86 r180 top value=316k
R58 "CRCW0805316KFKEA" 0805_HV1 4388.27,6572.5 r180 top value=316k
R59 "RT0603BRD0710KL" 0603S 3967.92,5227.62 r270 top value=10.0k
R60 "CRCW0805316KFKEA" 0805_HV1 4093.62,6574.86 r180 top value=316k
R61 "RT0603BRD0716K5L" 0603S 4130.03,5073.62 r90 top value=16.5k
R62 "CRCW0805316KFKEA" 0805_HV1 4534.82,6572.5 r0 top value=316k
R63 "RC0603JR-070RL" 0603S 3669.63,5407.8 r180 top value=0
R64 "RMCF0603ZT0R00" 0603S 4146.74,4954.66 r90 top value=0
R65 "RMCF0603ZT0R00" 0603S 4086.74,4954.66 r270 top value=0
R66 "RC0603FR-073K24L" 0603 3952.55,6571.67 r0 top value=3.24k
R67 "RC0603FR-100RL" FP-RC0603FR-100RL_0603-MFG 4430.29,3148.38 r270 top value=0
R68 "RC0603FR-100RL" FP-RC0603FR-100RL_0603-MFG 4233.28,2863.52 r180 top value=0
R69 "RC0603FR-100RL" FP-RC0603FR-100RL_0603-MFG 4232.78,2961 r0 top value=0
R70 "RC0603FR-100RL" FP-RC0603FR-100RL_0603-MFG 4407.2,3899.86 r180 top value=0
R71 "CRM2512-FX-2000ELF" 2512 1019.71,5575 r180 top value=200
R72 "RC1210JR-073M3L" 1210 786.49,6122 r90 top value=3.3Meg
R73 "RC0603FR-100RL" FP-RC0603FR-100RL_0603-MFG 4694.65,2755.78 r270 top value=0
R74 "MCR01MZPF10R0" 0402 4418.36,2675.31 r180 top value=10.0
R75 "RC0603FR-100RL" FP-RC0603FR-100RL_0603-MFG 4746.85,2755.96 r90 top value=0
R76 "RT0603DRE0710K6L" 0603 2430.8,3243.94 r270 top value=10.6k
R77 "RC0603JR-071K1L" 0603 2375.06,3134.32 r0 top value=1.1k
R78 "RC0603JR-07560RL" 0603 2829.84,2145.96 r0 top value=560
R79 "RC0603JR-07560RL" 0603 2832.23,2067.22 r0 top value=560
R80 "RC0603JR-07560RL" 0603 2834.84,1984.08 r0 top value=560
R81 "CRCW0603100KJNEAC" 0603 3267,4793 r90 top value=100k
R82 "CRCW0603100KJNEAC" 0603 3266.83,4929.42 r90 top value=100k
R83 "RC0603FR-07316KL" 0603 3087.47,3571.86 r180 top value=316k
R84 "RC0603FR-100RL" FP-RC0603FR-100RL_0603-MFG 4524,3821 r180 top value=0
R85 "CRCW060322K1FKEA" 0603L 4520.69,3909.14 r180 top value=22.1k
R86 "RC0603FR-100RL" FP-RC0603FR-100RL_0603-MFG 3851.74,3452.98 r180 top value=0
R87 "RC0603FR-100RL" FP-RC0603FR-100RL_0603-MFG 3851.74,3504.56 r180 top value=0
R88 "M55342K12B10E0T" 0603 4831.73,4778.73 r90 top value=10.0k
R89 "RC0603JR-074K7L" 0603S 4707.47,4891.2 r0 top value=4.7k
SH-J1 "2SN-BK-G" 2SN-BK-G 5071,6904 r90 top value=1x2
SH-J5 "2SN-BK-G" 2SN-BK-G 1841,5758 r270 top value=1x2
SH-J6 "2SN-BK-G" 2SN-BK-G 1851.46,5204.78 r270 top value=1x2
TP1 "TP_H0.45P0.75" TP_H045P075 4527.22,3168.28 r90 top
TP2 "TP_H0.45P0.75" TP_H045P075 4359.52,3081.3 r90 top
TP3 "TP_H0.45P0.75" TP_H045P075 4437,3701.97 r90 top
TP4 "TP_H0.45P0.75" TP_H045P075 4440.66,3963.62 r90 top
TP5 "TP_H0.45P0.75" TP_H045P075 4623.42,3020.55 r90 top
TP6 "TP_H0.45P0.75" TP_H045P075 4612,4005.45 r90 top
TP7 "TP_H0.45P0.75" TP_H045P075 4304.32,3078.27 r90 top
TP8 "TP_H0.45P0.75" TP_H045P075 4825.03,2803.13 r90 top
TP9 "TP_H0.45P0.75" TP_H045P075 4430.86,3235.66 r90 top
TP10 "TP_H0.45P0.75" TP_H045P075 3728.2,3449.73 r90 top
TP11 "TP_H0.45P0.75" TP_H045P075 3744.28,3571 r90 top
TP12 "TP_H0.45P0.75" TP_H045P075 3738.28,2580.3 r90 top
TP13 "TP_H0.45P0.75" TP_H045P075 3799,3571 r90 top
TP14 "5007" Keystone5007 2617.42,5222.83 r0 top
TP15 "TP_H0.45P0.75" TP_H045P075 4881.65,2801.37 r90 top
TP16 "5007" Keystone5007 3001.1,5224.36 r270 top
TP17 "TP_H0.45P0.75" TP_H045P075 3731.28,2750.23 r90 top
TP18 "TP_H0.45P0.75" TP_H045P075 4688.82,3020.55 r90 top
TP19 "TP_H0.45P0.75" TP_H045P075 3719.78,2358.55 r90 top
TP20 "TP_H0.45P0.75" TP_H045P075 3773.28,2358.55 r90 top
TP21 "5007" Keystone5007 3756.18,5217.29 r90 top
TP22 "TP_H0.45P0.75" TP_H045P075 4440.66,4017.66 r90 top
TP23 "5007" Keystone5007 4106.48,5208.18 r270 top
TP24 "TP_H0.45P0.75" TP_H045P075 3789.78,2625 r90 top
TP25 "TP_H0.45P0.75" TP_H045P075 4437,3641.41 r90 top
TP26 "TP_H0.45P0.75" TP_H045P075 3785.28,2750.23 r90 top
TP_AE "5007" Keystone5007 4597,4599 r90 top
TP_AGND "5017" Keystone_5017 3875.48,3909.55 r180 top
TP_AGND1 "5007" Keystone5007 3555.13,5113.6 r0 top
TP_AGND2 "5007" Keystone5007 3199.99,5071.62 r270 top
TP_AGND3 "5007" Keystone5007 4856.76,5436.34 r0 top
TP_Cgap "5007" Keystone5007 4432.27,5378.87 r90 top
TP_Latch "5007" Keystone5007 4611.79,5128.69 r90 top
TP_Vgap "5007" Keystone5007 3669.63,4973.95 r90 top
TP_VIN "S1751-46R" FP-S1751-46R_SMT_TEST_POINT_3MM25_1MM65-MFG 3349,4008.52 r180 top
TP_VSTRING "5007" Keystone5007 2632.4,4949.34 r0 top
U1 "TLV9054IDR" D0014A-MFG 3295.04,3521.86 r0 top
U2 "TLV387DBVR" DBV0005A-MFG 4120.26,3807.07 r90 top
U3 "LOG300RGT" RGT0016A-MFG 4576.23,2906.83 r90 top
U4 "UCC28881DR" D0007A_N 1742.36,3057.68 r90 top
U5 "TLV709A33DBVR" DBV0005A-MFG 1358.5,2703.35 r270 top
U6 "TLV9051IDBVR" DBV0005A-MFG 3373.62,4766.47 r270 top
U7 "SN74LVC1G14DCKT" DCK0005A_N 4628.82,4778.73 r270 top
U8 "TLV9022LRUG" RUG0010A-MFG 4632.47,4964.35 r180 top
U9 "AMC3330DWE" DWE0016A-MFG 2922.75,5797.92 r270 top
U10 "TLV6001IDBVR" DBV0005A_N 2824.12,5084.33 r180 top
U11 "AMC23C11DWVR" DWV0008A-MFG 4609.82,5770.96 r270 top
U12 "AMC3330DWE" DWE0016A-MFG 4049.85,5777.59 r270 top
U13 "TLV6001IDBVR" DBV0005A_N 3943.91,5073.62 r180 top
ZZ1 "This Assembly Note is for PCB labels only" AssemblyNoteLabel 692,7934 r0 top
ZZ2 "These assemblies are ESD sensitive, ESD precautions shall be observed." AssemblyNote 692,7834 r0 top
ZZ3 "These assemblies must be clean and free from flux and all contaminants. Use of no clean flux is not acceptable." AssemblyNote 692,7734 r0 top
ZZ4 "These assemblies must comply with workmanship standards IPC-A-610 Class 2, unless otherwise specified." AssemblyNote 1038,7634 r0 top

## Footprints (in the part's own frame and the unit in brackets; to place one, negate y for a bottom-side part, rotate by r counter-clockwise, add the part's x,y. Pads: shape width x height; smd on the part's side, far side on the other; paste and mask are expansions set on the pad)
2SN-BK-G [mil] "Samtec STEP model"
  round 1 on Mech3: 0(0,0)
  body extent -78,-39 79,39, height 188
0402 [mm] "0402 from SM-752 data"
  rect 0.8x0.6 smd: 1(-0.6,0) 2(0.6,0)
  silkscreen extent -1.22,-0.52 1.22,0.52, body extent -0.55,-0.3 0.55,0.3, height 0.6
0402S [mil] "Based on C0402S footprint from PADS legacy"
  rect 15x24 smd: 1(-20,0) 2(20,0)
  body extent -22,-12 22,12, height 24
0603 [mm] "0603 from SM-752 data"
  rect 1x0.95 smd: 1(-0.8,0) 2(0.8,0)
  silkscreen extent -1.52,-0.69 1.52,0.69, body extent -0.87,-0.47 0.87,0.47, height 1
0603AF [mm] "COILCRAFT"
  rect 0.64x1.02 smd: 1(-0.64,0) 2(0.64,0)
  silkscreen extent -0.13,-0.63 0.13,0.63, body extent -0.92,-0.56 0.92,0.56, height 0.9
0603L [mm] "0603 from SM-752 data"
  rect 0.8x0.85 smd: 1(-0.7,0) 2(0.7,0)
  silkscreen extent -0.07,-0.33 0.07,0.33, body extent -0.87,-0.47 0.87,0.47, height 1
0603LS_B1 [mm] "SMD, 2-Leads, Body 1.8x1.016mm"
  rrect16% 0.64x1.02 smd: 1(-0.64,0) 2(0.64,0)
  body extent -0.9,-0.51 0.9,0.51, height 1.11
0603LS_B2 [mm] "SMD, 2-Leads, Body 1.8x1.169mm"
  rrect16% 0.64x1.02 smd: 1(-0.64,0) 2(0.64,0)
  body extent -0.9,-0.58 0.9,0.58, height 1.11
0603S [mil]
  rect 20x35 smd: 1(-30,0) 2(30,0)
  body extent -34,-19 34,19, height 39
0805_HV1 [mm] "Custom footprint based on analyzing multiple manufacturer recommendations"
  rrect10% 1x1.25 smd: 1(-1,0) 2(1,0)
  silkscreen extent -0.2,-0.75 0.2,0.75, body extent -1.1,-0.72 1.1,0.73, height 1.45
0805L [mm] "0805 from SM-752 data"
  rect 1.1x1.4 smd: 1(-0.75,0) 2(0.75,0)
  body extent -1.1,-0.72 1.1,0.72, height 1.45
1206 [mm] "1206 from SM-752 data"
  rect 1.3x1.85 smd: 1(-1.45,0) 2(1.45,0)
  silkscreen extent -2.4,-1.21 2.4,1.21, body extent -1.7,-0.9 1.7,0.9, height 1.35
1210 [mm] "1210 from SM-752 data"
  rect 1.3x2.7 smd: 1(-1.45,0) 2(1.45,0)
  silkscreen extent -2.32,-1.57 2.32,1.57, body extent -1.7,-1.35 1.7,1.35, height 1.35
2010L [mm]
  rect 1.2x2.7 smd: 1(-2.2,0) 2(2.2,0)
  silkscreen extent -1.2,-1.25 1.2,1.25, body extent -2.73,-1.45 2.73,1.45, height 1.66
2512 [mm] "Chip Resistor, Body 6.3x3.2mm, IPC Medium Density"
  rect 1.3x3.4 smd: 1(-2.95,0) 2(2.95,0)
  silkscreen extent -1.9,-1.6 1.9,1.6, body extent -3.22,-1.67 3.22,1.67, height 0.71
AAAF5060QBFSURZGS [mm] "SMD, 6-Leads, Body 5x6mm, Pitch 2mm"
  rrect6% 3x1.6 smd: 1(-2.7,2) 2(-2.7,0) 3(-2.7,-2) 4(2.7,-2) 5(2.7,0) 6(2.7,2)
  silkscreen extent -2.5,-3.1 2.5,3.4, body extent -2.85,-3 2.85,3, height 2.3
AssemblyNote [mil] "Assembly Note"
AssemblyNoteLabel [mil] "Assembly Note for PCB Labels"
B32933_600x1500x2650 [mm] "Film cap"
  round 1.65 hole 1.1: 1(-11.25,0) 2(11.25,0)
  silkscreen extent -13.25,-3 13.25,3, body extent -13.25,-3 13.25,3, height 15
BoosterPack_40pin_J1J3 [mm] "Receptacle, 2.54mm, 10x2, TH"
  rrect6% 1.55x1.55 hole 1.02: 1(1.27,11.43)
  round 1.55 hole 1.02: 2(1.27,8.89) 3(1.27,6.35) 4(1.27,3.81) 5(1.27,1.27) 6(1.27,-1.27) 7(1.27,-3.81) 8(1.27,-6.35) 9(1.27,-8.89) 10(1.27,-11.43) 21(-1.27,11.43) 22(-1.27,8.89) 23(-1.27,6.35) 24(-1.27,3.81) 25(-1.27,1.27) 26(-1.27,-1.27) 27(-1.27,-3.81) 28(-1.27,-6.35) 29(-1.27,-8.89) 30(-1.27,-11.43)
  silkscreen extent -7.62,-12.95 7.62,12.95, body extent -2.48,-12.95 2.48,12.95, height 8.51
BoosterPack_40pin_J2J4 [mm] "Receptacle, 2.54mm, 10x2, TH"
  round 1.55 hole 1.02: 11(-1.27,-11.43) 12(-1.27,-8.89) 13(-1.27,-6.35) 14(-1.27,-3.81) 15(-1.27,-1.27) 16(-1.27,1.27) 17(-1.27,3.81) 18(-1.27,6.35) 19(-1.27,8.89) 20(-1.27,11.43) 31(1.27,-11.43) 32(1.27,-8.89) 33(1.27,-6.35) 34(1.27,-3.81) 35(1.27,-1.27) 36(1.27,1.27) 37(1.27,3.81) 38(1.27,6.35) 39(1.27,8.89) 40(1.27,11.43)
  silkscreen extent -7.62,-12.95 2.48,12.95, body extent -2.48,-12.95 2.48,12.95, height 8.51
CE_Mark_5mm [mil] "Minimum text height for CE Mark"
  silkscreen extent -138,-98 138,98
CKG57N [mm] "Chip Capacitor, Body 6.0x5.0x5.0mm,"
  rect 2x5 smd: 1(-2.95,0) 2(2.95,0)
  silkscreen extent -3.2,-2.8 3.2,2.8, body extent -3.3,-2.75 3.3,2.75, height 5.5
D0007A_N [mm] "SOIC, 7-Leads, Body 4.9x3.9mm, Pitch 1.27mm, IPC Medium Density"
  oval 1.45x0.6 smd: 1(-2.725,1.905) 2(-2.725,0.635) 3(-2.725,-0.635) 4(-2.725,-1.905) 5(2.725,-1.905) 6(2.725,-0.635) 8(2.725,1.905)
  silkscreen extent -3.32,-2.5 1.1,2.52, body extent -3.01,-2.45 3.01,2.45, height 1.75
D0014A-MFG [mm] "Recommended Land Pattern"
  rrect17% 1.55x0.6 smd paste+0 mask+0: 1(-2.7,3.81) 2(-2.7,2.54) 3(-2.7,1.27) 4(-2.7,0) 5(-2.7,-1.27) 6(-2.7,-2.54) 7(-2.7,-3.81) 8(2.7,-3.81) 9(2.7,-2.54) 10(2.7,-1.27) 11(2.7,0) 12(2.7,1.27) 13(2.7,2.54) 14(2.7,3.81)
  silkscreen extent -2.82,-4.38 1.5,4.81, body extent -3,-4.33 3,4.33, height 1.75
DBV0005A-MFG [mm] "Recommended Land Pattern"
  rrect17% 1.1x0.6 smd paste+0 mask+0: 1(-1.3,0.95) 2(-1.3,0) 3(-1.3,-0.95) 4(1.3,-0.95) 5(1.3,0.95)
  silkscreen extent -2.57,-1.53 0.87,1.53, body extent -1.4,-1.45 1.4,1.45, height 1.45
DBV0005A_N [mm] "SOT23, 5-Leads, Body 2.9x1.6mm, Pitch 0.95mm, Lead Span 2.8mm, IPC Medium Density"
  rrect17% 1x0.6 smd: 1(-1.375,0.95) 2(-1.375,0) 3(-1.375,-0.95) 4(1.375,-0.95) 5(1.375,0.95)
  silkscreen extent -0.25,-1.55 0.25,1.55, body extent -1.42,-1.46 1.42,1.46, height 1.09
DCK0005A_N [mm] "SOT353, 5-Leads, Body 2x1.3mm, Pitch 0.65mm, Lead Span 2.1mm, IPC Medium Density"
  rrect25% 0.85x0.4 smd: 1(-1.125,0.65) 2(-1.125,0) 3(-1.125,-0.65) 4(1.125,-0.65) 5(1.125,0.65)
  silkscreen extent -1.48,-1.02 0.55,1.1, body extent -1.14,-1 1.14,1, height 0.95
Diode_1408 [mm] "On Semi recommended land pattern for SOD-123"
  rect 1.75x2 smd: 1(-1.425,0) 2(1.425,0)
  silkscreen extent -2.97,-1.35 2.26,1.35, body extent -1.8,-1.05 1.8,1.05, height 1.35
DO-219AB [mm] "Vishay Semiconductor"
  rrect8% 1.3x1.4 smd: 1(-1.45,0) 2(1.45,0)
  silkscreen extent -1.9,-1.07 1.23,1.07, body extent -1.95,-0.95 1.95,0.95, height 1.09
DQK0006C [mm] "WSON"
  rrect12% 0.9x0.86 on Top Paste: 0(0,0.325)
  rrect34% 0.7x0.29 on Top Paste: 0(0.095,-0.65)
  rrect33% 0.45x0.3 smd: 1(-0.975,0.65) 2(-0.975,0) 3(-0.975,-0.65) 4(0.975,-0.65) 5(0.975,0) 6(0.975,0.65)
  rrect33% 0.75x0.3 smd paste-0.15: 7(0.095,-0.65)
  rrect11% 1x0.95 smd paste-0.5: 8(0,0.325)
  silkscreen extent -1.15,-1.15 1.15,1.15, body extent -1,-1 1,1, height 0.82
DWE0016A-MFG [mm]
  rrect17% 1.65x0.6 smd paste+0 mask+0: 1(-4.875,4.445) 2(-4.875,3.175) 3(-4.875,1.905) 4(-4.875,0.635) 5(-4.875,-0.635) 6(-4.875,-1.905) 7(-4.875,-3.175) 8(-4.875,-4.445) 9(4.875,-4.445) 10(4.875,-3.175) 11(4.875,-1.905) 12(4.875,-0.635) 13(4.875,0.635) 14(4.875,1.905) 15(4.875,3.175) 16(4.875,4.445)
  silkscreen extent -6.37,-5.25 3.5,5.25, body extent -5.8,-5.5 5.8,5.5, height 0.25
DWV0008A-MFG [mm]
  rrect17% 1.8x0.6 smd paste+0 mask+0: 1(-5.45,1.905) 2(-5.45,0.635) 3(-5.45,-0.635) 4(-5.45,-1.905) 5(5.45,-1.905) 6(5.45,-0.635) 7(5.45,0.635) 8(5.45,1.905)
  silkscreen extent -7.1,-2.98 3.8,2.98, body extent -6.45,-3.22 6.45,3.22, height 0.25
FCC_disclaimer [mil]
Fiducial10-30 [mm]
  round 1 smd mask+1: 1(0,0)
  F.CU keep-out circle w1.678: c0,0 r0.75
FP-4806_HEX_STNDFF_4-40-MFG [mil]
  body extent -142,-125 142,125, height 1000
FP-0476005.MR_SMT_FUSE_6MM1_2MM69-MFG [mm]
  rrect5% 1.96x3.15 smd paste+0 mask+0: 1(-2.45,0) 2(2.45,0)
  silkscreen extent -1.09,-1.47 1.09,1.47, body extent -3.53,-1.67 3.53,1.67, height 0.25
FP-C0603X102K5RAC7867_0603-MFG [mm]
  rrect12% 0.85x0.9 smd paste+0 mask+0: 1(-0.65,0) 2(0.65,0)
  silkscreen extent -0.88,-0.82 0.88,0.82, body extent -1.2,-0.6 1.2,0.6, height 0.25
FP-CR0603-10W-000T_0603-MFG [mm]
  rrect10% 1x1 smd paste+0 mask+0: 1(-0.8,0) 2(0.8,0)
  silkscreen extent -0.85,-0.9 0.85,0.9, body extent -1.4,-0.6 1.4,0.6, height 0.25
FP-GMC04X7R105K10NT_0402-MFG [mil]
  rrect19% 21x22 smd paste+0 mask+0: 1(-19,0) 2(19,0)
  silkscreen extent -21,-27 21,27, body extent -33,-15 33,15, height 10
FP-MOV-20D431K_RADIAL-MFG [mm]
  rrect5% 1.9x1.9 hole 1.25 paste-2539.97 mask+0: 1(-5,0)
  round 1.9 hole 1.25 paste-2539.97 mask+0: 2(5,0)
  silkscreen extent -11.5,-2.8 11.5,2.8, body extent -11.6,-2.9 11.6,2.9, height 0.25
FP-RC0603FR-100RL_0603-MFG [mm]
  rrect13% 0.9x0.8 smd paste+0 mask+0: 1(-0.85,0) 2(0.85,0)
  silkscreen extent 0,-0.45 0,0.45, body extent -1.4,-0.55 1.4,0.55, height 0.25
FP-S1751-46R_SMT_TEST_POINT_3MM25_1MM65-MFG [mm]
  rrect5% 3.45x1.85 smd paste+0 mask+0: 1(0,0)
  silkscreen extent -2.12,-1.33 2.12,1.33, body extent -1.83,-1.02 1.83,1.02, height 0.25
IEC_HighVoltage_Small [mil]
  silkscreen extent -107,-88 107,97
IEC_HotSurface_Small [mil]
  silkscreen extent -107,-93 107,92
Keystone5005 [mil] "Keystone Compact loops"
  round 87 hole 63: 1(0,0)
  silkscreen extent -70,-70 70,70, body extent -63,-63 62,63, height 225
Keystone5006 [mil] "Keystone Compact loops"
  round 87 hole 63: 1(0,0)
  silkscreen extent -70,-70 70,70, body extent -63,-63 62,63, height 225
Keystone5007 [mil] "Keystone Compact loops"
  round 87 hole 63: 1(0,0)
  silkscreen extent -70,-70 70,70, body extent -63,-63 62,63, height 225
Keystone5010 [mil] "Keystone Multipurpose loops"
  round 87 hole 63: 1(0,0)
  silkscreen extent -70,-70 70,70, body extent -63,-63 63,62, height 319
Keystone5011 [mil] "Keystone Multipurpose loops"
  round 87 hole 63: 1(0,0)
  silkscreen extent -70,-70 70,70, body extent -63,-63 63,62, height 319
Keystone_5017 [mm] "PC Test Point, SMT"
  rrect6% 3.43x1.78 smd: 1(0,0)
  body extent -1.35,-0.51 1.35,0.51, height 1.51
NPTH125mil [mil]
  round 120 hole 125 unplated mask+15: 1(0,0)
On-Shore_ED120_2DS [mm] "ONSHORE"
  rrect5% 2x2 hole 1.25: 1(-2.54,0)
  round 2 hole 1.25: 2(2.54,0)
  silkscreen extent -5.6,-4 5.12,5, body extent -5.78,-4 5.08,5, height 13
RELAY_RTB14 [mm] "TYCO"
  round 1.8 hole 1.3: 1(-11.938,-3.81) 2(4.877,-3.81) 4(8.382,3.81) 5(-11.938,3.81)
  round 1.8 hole 1.295: 3(11.887,-3.81)
  silkscreen extent -14.48,-6.35 14.48,6.35, body extent -14.48,-6.35 14.48,6.35, height 15.75
RGT0016A-MFG [mm]
  rrect42% 0.6x0.24 smd paste+0 mask+0: 1(-1.4,0.75) 2(-1.4,0.25) 3(-1.4,-0.25) 4(-1.4,-0.75) 9(1.4,-0.75) 10(1.4,-0.25) 11(1.4,0.25) 12(1.4,0.75)
  rrect42% 0.24x0.6 smd paste+0 mask+0: 5(-0.75,-1.4) 6(-0.25,-1.4) 7(0.25,-1.4) 8(0.75,-1.4) 13(0.75,1.4) 14(0.25,1.4) 15(-0.25,1.4) 16(-0.75,1.4)
  rrect7% 1.45x1.45 smd paste-1000 mask+0: 17(0,0)
  silkscreen extent -2.4,-1.55 1.55,1.55, body extent -1.8,-1.8 1.8,1.8, height 0.25
RUG0010A-MFG [mm]
  rrect33% 0.3x0.575 smd paste-1000 mask+0: 1(-0.75,-0.637) 4(0.75,-0.637) 6(0.75,0.637) 9(-0.75,0.637)
  rrect40% 0.25x0.575 smd paste-1000 mask+0: 2(-0.25,-0.637) 3(0.25,-0.637) 7(0.25,0.637) 8(-0.25,0.637)
  rrect29% 0.63x0.35 smd paste-1000 mask+0: 5(0.86,0) 10(-0.86,0)
  silkscreen extent -1.25,-1.62 1.25,0.77, body extent -1.28,-1.02 1.28,1.02, height 0.25
SMA_Bi [mm] "SMD, 2-Leads, Body 4.275x2.575mm"
  rect 1.4x1.64 smd: 1(-2.015,0) 2(2.015,0)
  silkscreen extent -2.3,-1.45 2.3,1.45, body extent -2.52,-1.45 2.52,1.45, height 2.65
SMB [mil] "Molded Diode, 2-Leads, Body 5.4x3.6mm, IPC Medium Density, based on OnSemi component dimensions"
  rect 85x107.99 smd: 1(-87.01,0) 2(87.01,0)
  silkscreen extent -155,-82 125,82, body extent -106,-71 106,71, height 91
SOD-123 [mm] "On Semi recommended land pattern"
  rect 0.915x1.22 smd: 1(-1.637,0) 2(1.637,0)
  silkscreen extent -2.41,-1.08 2.03,1.08, body extent -1.93,-0.9 1.93,0.9, height 1.35
TI_Stacked_Overlay_Small [mil]
  silkscreen extent -418,-98 418,98
TP_H045P075 [mm] "TP_H0.45P0.75"
  round 0.75 hole 0.45: 1(0,0)
TSW-102-07-G-S [mm] "Samtec 100mil, 1x2, 230 mil above insulator"
  rrect50% 1.65x1.65 hole 1.016: 1(-1.27,0)
  round 1.65 hole 1.016: 2(1.27,0)
  body extent -2.54,-1.27 2.54,1.27, height 8.38
WE-LQ_1812 [mm] "SMD, 2-Leads, Body 4.5x3.2mm"
  rrect5% 2x3.6 smd: 1(-1.7,0) 2(1.7,0)
  silkscreen extent -0.4,-1.8 0.4,1.8, body extent -2.25,-1.6 2.25,1.6, height 2.6
WEEE_Minimum [mil] "WEEElie bin"
  silkscreen extent -95,-172 99,104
